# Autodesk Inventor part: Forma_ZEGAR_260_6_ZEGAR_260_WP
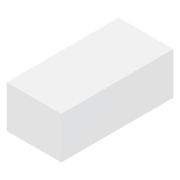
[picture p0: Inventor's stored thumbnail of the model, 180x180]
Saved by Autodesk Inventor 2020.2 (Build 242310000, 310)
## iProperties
Created: 2015-01
Part Number: Forma_ZEGAR_260_6_ZEGAR_260_WP
Material: Ogólny
Document SubType Name: Modeling
Designer: F.Stasiak
Density: 1 g/cm^3
Appearance: Domyślna
Catalog Web Link: www.expertbooks.pl
Manager: www.cadconsulting.pl
Company: Fabian Stasiak CAD Consulting
d0: -30.000 mm
d1: 39.000 mm
d2: 39.000 mm
d3: 80.000 mm
d4: 80.000 mm
d5: 60.000 mm
d6: 0.00 deg
Xmin: -39.000 mm
Ymin: -80.000 mm
Zmin: -30.000 mm
Xmax: 39.000 mm
Ymax: 80.000 mm
Zmax: 30.000 mm
Author: F.Stasiak
Subject: Zbiór ćwiczeń. Autodesk Inventor 2020. Kurs Professional
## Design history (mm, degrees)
sketch "Szkic1"
  geometry: L1 (-39, 80)-(39, 80); L2 (39, 80)-(39, -80); L3 (39, -80)-(-39, -80); L4 (-39, -80)-(-39, 80); 1 further point
  constraints: 8 end point, 2 parallel, 1 horizontal, 1 perpendicular, 1 other
  dimensions: "d1" = 39 distance from line of L4 point (0, 0) (= -Xmin); "d2" = 39 distance from line of L2 point (0, 0) (= Xmax); "d3" = 80 distance from line of L3 point (0, 0) (= -Ymin); "d4" = 80 distance from line of L1 point (0, 0) (= Ymax)
extrude "Wyciągnięcie proste1" join sketch "Szkic1" distance "d5" = 60 (= Zmax - Zmin); taper "d6" = 0 deg
node "Bryła1"
other parameters: "Xmin" = -39 [user parameter; used in 1 equation term], "Ymin" = -80 [user parameter; used in 1 equation term], "Zmin" = -30 [user parameter; used in 1 equation term], "Xmax" = 39 [user parameter; used in 1 equation term], "Ymax" = 80 [user parameter; used in 1 equation term], "Zmax" = 30 [user parameter; used in 1 equation term], "d0" = -30
